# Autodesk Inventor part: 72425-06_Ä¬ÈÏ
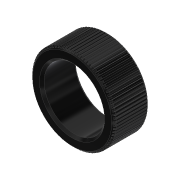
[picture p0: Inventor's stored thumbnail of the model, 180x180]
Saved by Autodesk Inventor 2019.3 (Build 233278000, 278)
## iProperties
Created: 2010-06
Part Number: 72425-06_Ä¬ÈÏ
Material: Ogólny
Document SubType Name: Modeling
Designer: CADENGINEERING4
Density: 1 g/cm^3
Appearance: Gładki — czarny
Author: CADENGINEERING4
Revision Number: ÈÎºÎ
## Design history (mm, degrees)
feature "NONE"
node "Bryła1"
